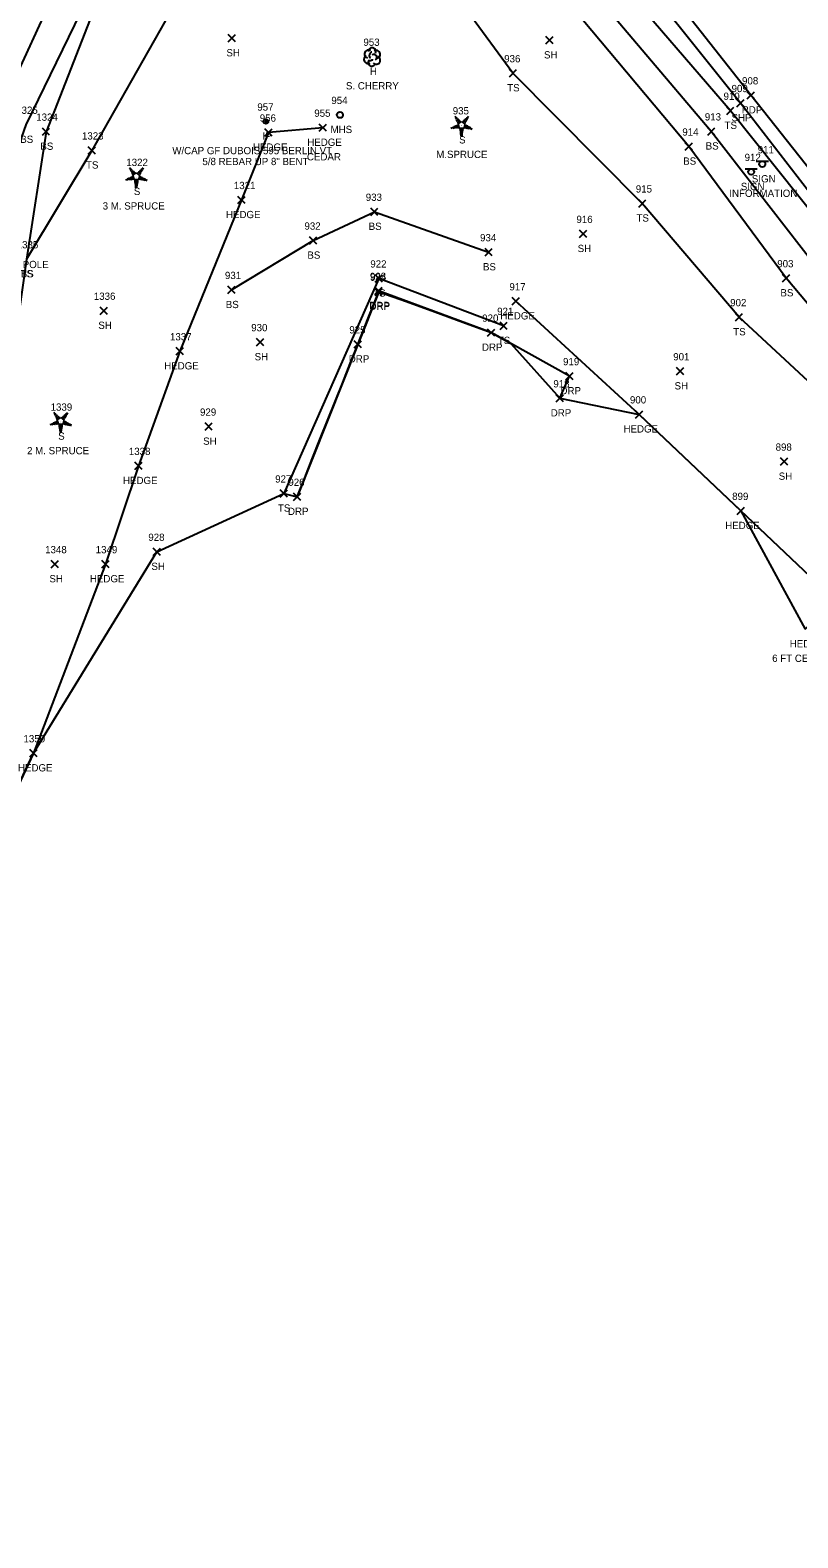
# Model space of a CAD drawing. Extents: x 1623612 to 1625808, y 621345 to 627748.
# Drawn here: x 1624694.8 to 1624906.2, y 625687.8 to 626102.9 of the extents above; entities that cross this region are included whole.
import ezdxf

# ---------------------------------------------------------------- set-up
doc = ezdxf.new("R2010")
doc.units = 0
for name, color, linetype in [('L_A', 7, 'Continuous'), ('L_C', 7, 'Continuous'), ('L_I', 7, 'Continuous'), ('L_TIC', 7, 'Continuous'), ('LAHR', 7, 'Continuous'), ('LELB', 7, 'Continuous'), ('LSOGP', 7, 'Continuous'), ('LTC', 7, 'Continuous'), ('LTD', 7, 'Continuous'), ('M_A', 7, 'Continuous'), ('M_C', 7, 'Continuous'), ('M_I', 7, 'Continuous'), ('MPIR', 7, 'Continuous'), ('P_A', 7, 'Continuous'), ('P_I', 7, 'Continuous'), ('P_TIC', 7, 'Continuous'), ('PET', 7, 'Continuous'), ('PSP', 7, 'Continuous'), ('R_A', 7, 'Continuous'), ('R_I', 7, 'Continuous'), ('R_TIC', 7, 'Continuous'), ('RDP', 7, 'Continuous'), ('S_A', 7, 'Continuous'), ('S_C', 7, 'Continuous'), ('S_I', 7, 'Continuous'), ('SSGN', 7, 'Continuous'), ('U_A', 7, 'Continuous'), ('U_I', 7, 'Continuous'), ('USMH', 7, 'Continuous')]:
    doc.layers.add(name, color=color, linetype=linetype)

msp = doc.modelspace()

# ---------------------------------------------------------------- linework, layer by layer
at = {"layer": 'L_TIC'}
for points in [[(1624749.37, 626099.7), (1624751.37, 626101.7)], [(1624751.37, 626099.7), (1624749.37, 626101.7)], [(1624836.83, 626099.13), (1624838.83, 626101.13)], [(1624838.83, 626099.13), (1624836.83, 626101.13)], [(1624826.77, 626090.06), (1624828.77, 626092.06)], [(1624828.77, 626090.06), (1624826.77, 626092.06)], [(1624886.64, 626079.72), (1624888.64, 626081.72)], [(1624888.64, 626079.72), (1624886.64, 626081.72)], [(1624774.42, 626075.07), (1624776.42, 626077.07)], [(1624776.42, 626075.07), (1624774.42, 626077.07)], [(1624698.16, 626073.97), (1624700.16, 626075.97)], [(1624700.16, 626073.97), (1624698.16, 626075.97)], [(1624759.46, 626073.73), (1624761.46, 626075.73)], [(1624761.46, 626073.73), (1624759.46, 626075.73)], [(1624881.4, 626074.05), (1624883.4, 626076.05)], [(1624883.4, 626074.05), (1624881.4, 626076.05)], [(1624710.77, 626068.81), (1624712.77, 626070.81)], [(1624712.77, 626068.81), (1624710.77, 626070.81)], [(1624875.22, 626069.88), (1624877.22, 626071.88)], [(1624877.22, 626069.88), (1624875.22, 626071.88)], [(1624752.03, 626055.16), (1624754.03, 626057.16)], [(1624754.03, 626055.16), (1624752.03, 626057.16)], [(1624862.39, 626054.21), (1624864.39, 626056.21)], [(1624864.39, 626054.21), (1624862.39, 626056.21)], [(1624788.59, 626051.92), (1624790.59, 626053.92)], [(1624790.59, 626051.92), (1624788.59, 626053.92)], [(1624846.1, 626045.82), (1624848.1, 626047.82)], [(1624848.1, 626045.82), (1624846.1, 626047.82)], [(1624771.71, 626043.99), (1624773.71, 626045.99)], [(1624773.71, 626043.99), (1624771.71, 626045.99)], [(1624820.07, 626040.79), (1624822.07, 626042.79)], [(1624822.07, 626040.79), (1624820.07, 626042.79)], [(1624789.84, 626033.56), (1624791.84, 626035.56)], [(1624791.84, 626033.56), (1624789.84, 626035.56)], [(1624902, 626033.62), (1624904, 626035.62)], [(1624904, 626033.62), (1624902, 626035.62)], [(1624749.23, 626030.39), (1624751.23, 626032.39)], [(1624751.23, 626030.39), (1624749.23, 626032.39)], [(1624827.59, 626027.27), (1624829.59, 626029.27)], [(1624829.59, 626027.27), (1624827.59, 626029.27)], [(1624714.08, 626024.67), (1624716.08, 626026.67)], [(1624716.08, 626024.67), (1624714.08, 626026.67)], [(1624889.03, 626022.9), (1624891.03, 626024.9)], [(1624891.03, 626022.9), (1624889.03, 626024.9)], [(1624824.2, 626020.51), (1624826.2, 626022.51)], [(1624826.2, 626020.51), (1624824.2, 626022.51)], [(1624735.01, 626013.51), (1624737.01, 626015.51)], [(1624737.01, 626013.51), (1624735.01, 626015.51)], [(1624757.13, 626016.02), (1624759.13, 626018.02)], [(1624759.13, 626016.02), (1624757.13, 626018.02)], [(1624872.79, 626008), (1624874.79, 626010)], [(1624874.79, 626008), (1624872.79, 626010)], [(1624861.52, 625996.14), (1624863.52, 625998.14)], [(1624863.52, 625996.14), (1624861.52, 625998.14)], [(1624742.95, 625992.77), (1624744.95, 625994.77)], [(1624744.95, 625992.77), (1624742.95, 625994.77)], [(1624723.67, 625981.95), (1624725.67, 625983.95)], [(1624725.67, 625981.95), (1624723.67, 625983.95)], [(1624901.47, 625983.13), (1624903.47, 625985.13)], [(1624903.47, 625983.13), (1624901.47, 625985.13)], [(1624763.64, 625974.36), (1624765.64, 625976.36)], [(1624765.64, 625974.36), (1624763.64, 625976.36)], [(1624889.51, 625969.57), (1624891.51, 625971.57)], [(1624891.51, 625969.57), (1624889.51, 625971.57)], [(1624700.61, 625954.9), (1624702.61, 625956.9)], [(1624702.61, 625954.9), (1624700.61, 625956.9)], [(1624714.54, 625954.9), (1624716.54, 625956.9)], [(1624716.54, 625954.9), (1624714.54, 625956.9)], [(1624728.7, 625958.31), (1624730.7, 625960.31)], [(1624730.7, 625958.31), (1624728.7, 625960.31)], [(1624694.74, 625902.84), (1624696.74, 625904.84)], [(1624696.74, 625902.84), (1624694.74, 625904.84)]]:
    msp.add_lwpolyline(points, dxfattribs=at)
at = {"layer": 'LAHR'}
for points in [[(1624775.42, 626076.07), (1624760.46, 626074.73), (1624753.03, 626056.16), (1624736.01, 626014.51), (1624724.67, 625982.95), (1624715.54, 625955.9), (1624695.74, 625903.84), (1624670.26, 625849.95), (1624662.52, 625817.48), (1624651.69, 625796.18)], [(1624908.29, 625937.99), (1624916.64, 625945.86), (1624890.51, 625970.57), (1624862.52, 625997.14), (1624828.59, 626028.27)]]:
    msp.add_lwpolyline(points, dxfattribs=at)
at = {"layer": 'LELB'}
for points in [[(1624922.62, 625919.78), (1624947.1, 625948.56), (1624957.29, 625967.96), (1624961.07, 625979.24), (1624958.14, 625988.32), (1624939.98, 626014.97), (1624913.35, 626048.53), (1624887.64, 626080.72), (1624849.69, 626124.89), (1624827.87, 626147.28), (1624809.41, 626168.54), (1624784.36, 626180.38), (1624768.54, 626181.82), (1624752.66, 626178.59), (1624735.62, 626165.38), (1624717.35, 626142.72), (1624703.97, 626118.88), (1624686.38, 626080.62)], [(1624955.96, 625983.78), (1624934.11, 626011.11), (1624911.27, 626037.79), (1624882.4, 626075.05), (1624844.35, 626119.9), (1624824.36, 626144.8), (1624806.17, 626164.83), (1624787.45, 626176.55), (1624783.93, 626178.73), (1624767.98, 626179.73), (1624754.07, 626176), (1624742, 626162.74), (1624739.77, 626159.16), (1624724.1, 626139.19), (1624712.05, 626114.81), (1624693.63, 626076.88), (1624682.43, 626045.31), (1624675.97, 626009.13), (1624661.01, 625972.63), (1624643.83, 625915.97), (1624628.3, 625870.19), (1624627.01, 625849.3)], [(1624955.96, 625983.78), (1624951.7, 625981.09), (1624926.74, 626006.44), (1624903, 626034.62), (1624876.22, 626070.88), (1624844.75, 626108.46), (1624819.16, 626140.11), (1624799.87, 626157.38), (1624783.22, 626162.54), (1624755.55, 626163.6), (1624745.94, 626159.17), (1624742.5, 626157.44), (1624728.24, 626136.03), (1624714.3, 626113.6), (1624699.16, 626074.97), (1624693.78, 626039.85), (1624688.78, 626004.07), (1624672.44, 625966.06), (1624654.5, 625913.12), (1624647.49, 625863.39), (1624632.05, 625839.96), (1624633.8, 625804.37), (1624607.9, 625781.97), (1624576.85, 625750.09)], [(1624950.51, 625967.41), (1624917.97, 625998.05), (1624890.03, 626023.9), (1624863.39, 626055.21), (1624827.77, 626091.06), (1624802.93, 626124.92), (1624791, 626136.13), (1624749.2, 626141.33), (1624736.73, 626113.9), (1624711.77, 626069.81), (1624693.78, 626039.85)], [(1624750.23, 626031.39), (1624772.71, 626044.99), (1624789.59, 626052.92), (1624821.07, 626041.79)], [(1624825.2, 626021.51), (1624790.84, 626034.56), (1624764.64, 625975.36)]]:
    msp.add_lwpolyline(points, dxfattribs=at)
at = {"layer": 'LSOGP'}
msp.add_lwpolyline([(1624670.26, 625849.95), (1624695.74, 625903.84), (1624729.7, 625959.31), (1624764.64, 625975.36), (1624768.33, 625974.45), (1624770.42, 625979.69), (1624772.51, 625984.94), (1624774.6, 625990.19), (1624776.69, 625995.43), (1624778.79, 626000.68), (1624780.88, 626005.93), (1624782.97, 626011.18), (1624785.06, 626016.42), (1624787.93, 626023.66), (1624790.79, 626030.91), (1624798.48, 626028.25), (1624806.24, 626025.38), (1624813.99, 626022.51), (1624821.75, 626019.64), (1624827.15, 626016.64), (1624840.69, 626001.56), (1624862.52, 625997.14), (1624890.51, 625970.57), (1624908.29, 625937.99)], dxfattribs=at)
at = {"layer": 'LTC'}
for p, q in [((1624811.74, 626078.92), (1624812.09, 626079.18)), ((1624811.95, 626078.46), (1624812.48, 626078.84)), ((1624812.14, 626076.85), (1624812.47, 626075.83)), ((1624812.16, 626077.99), (1624812.86, 626078.5)), ((1624812.37, 626077.53), (1624813.25, 626078.17)), ((1624812.59, 626077.07), (1624813.6, 626077.81)), ((1624812.59, 626077.07), (1624812.98, 626075.88)), ((1624813.6, 626077.81), (1624814.6, 626077.08)), ((1624814.02, 626078.12), (1624814.83, 626077.53)), ((1624814.6, 626077.08), (1624814.21, 626075.88)), ((1624814.4, 626078.47), (1624815.08, 626077.97)), ((1624815.04, 626076.81), (1624814.7, 626075.77)), ((1624814.77, 626078.82), (1624815.32, 626078.42)), ((1624815.14, 626079.17), (1624815.56, 626078.86)), ((1624810.77, 626076.2), (1624810.92, 626075.74)), ((1624811.23, 626076.42), (1624811.44, 626075.77)), ((1624811.68, 626076.64), (1624811.95, 626075.8)), ((1624814.21, 626075.88), (1624812.98, 626075.88)), ((1624814.17, 626075.38), (1624813.03, 626075.38)), ((1624814.09, 626074.88), (1624813.1, 626074.88)), ((1624814, 626074.38), (1624813.17, 626074.38)), ((1624813.92, 626073.88), (1624813.25, 626073.88)), ((1624815.48, 626076.56), (1624815.2, 626075.68)), ((1624815.93, 626076.31), (1624815.69, 626075.58)), ((1624816.37, 626076.06), (1624816.19, 626075.49)), ((1624722.16, 626064.74), (1624722.52, 626065)), ((1624722.37, 626064.28), (1624722.9, 626064.66)), ((1624722.58, 626063.81), (1624723.29, 626064.32)), ((1624724.82, 626064.29), (1624725.5, 626063.79)), ((1624725.19, 626064.63), (1624725.74, 626064.23)), ((1624725.56, 626064.98), (1624725.98, 626064.68)), ((1624721.2, 626062.02), (1624721.35, 626061.55)), ((1624721.65, 626062.24), (1624721.86, 626061.59)), ((1624722.11, 626062.45), (1624722.38, 626061.62)), ((1624722.56, 626062.67), (1624722.89, 626061.65)), ((1624722.79, 626063.34), (1624723.67, 626063.98)), ((1624723.02, 626062.89), (1624724.03, 626063.62)), ((1624723.02, 626062.89), (1624723.4, 626061.7)), ((1624724.63, 626061.7), (1624723.4, 626061.7)), ((1624724.6, 626061.2), (1624723.45, 626061.2)), ((1624724.51, 626060.7), (1624723.52, 626060.7)), ((1624724.43, 626060.2), (1624723.6, 626060.2)), ((1624724.03, 626063.62), (1624725.03, 626062.9)), ((1624724.45, 626063.94), (1624725.26, 626063.35)), ((1624725.03, 626062.9), (1624724.63, 626061.7)), ((1624725.46, 626062.63), (1624725.13, 626061.59)), ((1624725.91, 626062.38), (1624725.62, 626061.49)), ((1624726.35, 626062.13), (1624726.12, 626061.4)), ((1624726.8, 626061.88), (1624726.61, 626061.3)), ((1624724.34, 626059.7), (1624723.67, 626059.7)), ((1624700.36, 625994.63), (1624700.52, 625994.16)), ((1624700.82, 625994.85), (1624701.03, 625994.2)), ((1624701.27, 625995.07), (1624701.55, 625994.23)), ((1624701.33, 625997.35), (1624701.69, 625997.61)), ((1624701.54, 625996.89), (1624702.07, 625997.27)), ((1624701.73, 625995.28), (1624702.06, 625994.26)), ((1624701.75, 625996.42), (1624702.45, 625996.93)), ((1624701.96, 625995.96), (1624702.84, 625996.59)), ((1624702.18, 625995.5), (1624703.2, 625996.24)), ((1624702.18, 625995.5), (1624702.57, 625994.31)), ((1624703.8, 625994.31), (1624702.57, 625994.31)), ((1624703.76, 625993.81), (1624702.62, 625993.81)), ((1624703.2, 625996.24), (1624704.19, 625995.51)), ((1624703.62, 625996.55), (1624704.43, 625995.96)), ((1624704.19, 625995.51), (1624703.8, 625994.31)), ((1624703.99, 625996.9), (1624704.67, 625996.4)), ((1624704.63, 625995.24), (1624704.29, 625994.2)), ((1624704.36, 625997.25), (1624704.91, 625996.85)), ((1624704.73, 625997.59), (1624705.15, 625997.29)), ((1624705.07, 625994.99), (1624704.79, 625994.1)), ((1624705.52, 625994.74), (1624705.28, 625994.01)), ((1624705.96, 625994.49), (1624705.78, 625993.91)), ((1624703.68, 625993.31), (1624702.69, 625993.31)), ((1624703.6, 625992.81), (1624702.76, 625992.81)), ((1624703.51, 625992.31), (1624702.84, 625992.31))]:
    msp.add_line(p, q, dxfattribs=at)
at = {"layer": 'LTD'}
msp.add_line((1624788.94, 626095.6), (1624788.94, 626095.6), dxfattribs=at)
msp.add_line((1624788.94, 626095.6), (1624788.94, 626095.6), dxfattribs=at)
msp.add_arc((1624788.99, 626097.04), 1.05, 335.5272, 180.9563, dxfattribs=at)
for centre, major_axis, ratio, start_param, end_param in [((1624788.15, 626096.27), (1.21, -0.51), 0.895232, 1.570796, 4.712389), ((1624789.98, 626096.18), (-1.14, -0.48), 0.949671, 1.570796, 4.712389), ((1624787.86, 626094.89), (0.58, -1.04), 0.959034, 3.141593, 6.283185), ((1624788.94, 626094.1), (0.26, 1.06), 0.942809, 1.570796, 4.712389), ((1624788.48, 626094.85), (-0.625, -0.083), 0.423636, 0, 3.141593), ((1624788.73, 626096.06), (-0.208, -0.792), 0.645439, 3.141593, 6.283185), ((1624789.44, 626095.43), (-0.5, 0.667), 0.989748, 3.141593, 6.283185), ((1624789.94, 626094.77), (-1.09, 0.79), 0.841452, 1.570796, 4.712389)]:
    msp.add_ellipse(centre, major_axis=major_axis, ratio=ratio, start_param=start_param, end_param=end_param, dxfattribs=at)
at = {"layer": 'MPIR'}
for radius in [0.625, 0.0833]:
    msp.add_circle((1624759.73, 626077.76), radius, dxfattribs=at)
at = {"layer": 'P_TIC'}
for points in [[(1624892.3, 626083.98), (1624894.3, 626085.98)], [(1624894.3, 626083.98), (1624892.3, 626085.98)], [(1624889.43, 626081.85), (1624891.43, 626083.85)], [(1624891.43, 626081.85), (1624889.43, 626083.85)]]:
    msp.add_lwpolyline(points, dxfattribs=at)
at = {"layer": 'PET'}
msp.add_lwpolyline([(1625203.84, 625692.06), (1625178.56, 625725.93), (1625159.1, 625752.13), (1625138.75, 625779.51), (1625115.85, 625810.21), (1625086.53, 625849.64), (1625062.28, 625882.29), (1625040.04, 625911.41), (1625011.87, 625940.67), (1624992.38, 625961.15), (1624963.94, 625995.04), (1624945.44, 626018.77), (1624918.36, 626053.4), (1624893.3, 626084.98), (1624858.44, 626129.32)], dxfattribs=at)
at = {"layer": 'PSP'}
msp.add_lwpolyline([(1625197.89, 625687.83), (1625193.57, 625693.81), (1625173.65, 625722.07), (1625153.52, 625749.21), (1625132.81, 625774.23), (1625108.64, 625805.39), (1625079.11, 625843.61), (1625053.93, 625876.29), (1625030.83, 625905.94), (1625006.8, 625934.64), (1624989.43, 625958.35), (1624960.91, 625992.11), (1624942.41, 626016.35), (1624915.38, 626050.56), (1624890.43, 626082.85), (1624855.5, 626126.62)], dxfattribs=at)
at = {"layer": 'R_TIC'}
for points in [[(1624789.73, 626030.13), (1624791.73, 626032.13)], [(1624791.73, 626030.13), (1624789.73, 626032.13)], [(1624789.79, 626029.91), (1624791.79, 626031.91)], [(1624791.79, 626029.91), (1624789.79, 626031.91)], [(1624820.75, 626018.64), (1624822.75, 626020.64)], [(1624822.75, 626018.64), (1624820.75, 626020.64)], [(1624784.06, 626015.42), (1624786.06, 626017.42)], [(1624786.06, 626015.42), (1624784.06, 626017.42)], [(1624842.36, 626006.66), (1624844.36, 626008.66)], [(1624844.36, 626006.66), (1624842.36, 626008.66)], [(1624839.69, 626000.56), (1624841.69, 626002.56)], [(1624841.69, 626000.56), (1624839.69, 626002.56)], [(1624767.33, 625973.45), (1624769.33, 625975.45)], [(1624769.33, 625973.45), (1624767.33, 625975.45)]]:
    msp.add_lwpolyline(points, dxfattribs=at)
at = {"layer": 'RDP'}
msp.add_lwpolyline([(1624840.69, 626001.56), (1624843.36, 626007.66), (1624821.75, 626019.64), (1624790.73, 626031.13), (1624790.79, 626030.91), (1624785.06, 626016.42), (1624768.33, 625974.45)], dxfattribs=at)
at = {"layer": 'SSGN'}
for p, q in [((1624891.74, 626064.74), (1624895.07, 626064.74)), ((1624894.78, 626066.86), (1624898.11, 626066.86)), ((1624896.42, 626066.03), (1624896.42, 626066.03)), ((1624893.38, 626063.91), (1624893.38, 626063.91))]:
    msp.add_line(p, q, dxfattribs=at)
for centre in [(1624893.38, 626063.91), (1624896.42, 626066.03)]:
    msp.add_circle(centre, 0.833, dxfattribs=at)
at = {"layer": 'USMH'}
for p, q in [((1624780.12, 626079.58), (1624780.12, 626079.58)), ((1624780.95, 626079.58), (1624780.95, 626079.58))]:
    msp.add_line(p, q, dxfattribs=at)
msp.add_circle((1624780.12, 626079.58), 0.833, dxfattribs=at)

# ---------------------------------------------------------------- texts
at = {"layer": 'L_A'}
for s, p in [('SH', (1624748.85, 626095.7)), ('SH', (1624836.32, 626095.13)), ('H', (1624788.37, 626090.6)), ('TS', (1624826.18, 626086.06)), ('TS', (1624886.05, 626075.72)), ('BS', (1624692.07, 626071.88)), ('HEDGE', (1624771.12, 626071.07)), ('S', (1624812.93, 626071.72)), ('BS', (1624697.6, 626069.97)), ('HEDGE', (1624756.16, 626069.73)), ('BS', (1624880.85, 626070.05)), ('TS', (1624710.18, 626064.81)), ('BS', (1624874.66, 626065.88)), ('S', (1624723.35, 626057.53)), ('HEDGE', (1624748.73, 626051.16)), ('TS', (1624861.8, 626050.21)), ('BS', (1624788.03, 626047.92)), ('SH', (1624845.59, 626041.82)), ('BS', (1624771.15, 626039.99)), ('TS', (1624692.19, 626034.85)), ('BS', (1624692.22, 626034.85)), ('BS', (1624819.51, 626036.79)), ('TS', (1624789.25, 626029.56)), ('BS', (1624901.44, 626029.62)), ('BS', (1624748.67, 626026.39)), ('HEDGE', (1624824.29, 626023.27)), ('SH', (1624713.57, 626020.67)), ('TS', (1624888.44, 626018.9)), ('TS', (1624823.61, 626016.51)), ('HEDGE', (1624731.71, 626009.51)), ('SH', (1624756.62, 626012.02)), ('SH', (1624872.28, 626004)), ('HEDGE', (1624858.22, 625992.14)), ('S', (1624702.52, 625990.15)), ('SH', (1624742.44, 625988.77)), ('HEDGE', (1624720.37, 625977.95)), ('SH', (1624900.96, 625979.13)), ('TS', (1624763.05, 625970.36)), ('HEDGE', (1624886.22, 625965.57)), ('SH', (1624728.19, 625954.31)), ('SH', (1624700.1, 625950.9)), ('HEDGE', (1624711.24, 625950.9)), ('HEDGE', (1624903.99, 625932.99)), ('HEDGE', (1624691.44, 625898.84))]:
    msp.add_text(s, height=2, dxfattribs=at).set_placement(p)
at = {"layer": 'L_C'}
for s, p in [('S. CHERRY', (1624781.76, 626086.6)), ('CEDAR', (1624771.03, 626067.07)), ('M.SPRUCE', (1624806.63, 626067.72)), ('3 M. SPRUCE', (1624714.77, 626053.53)), ('2 M. SPRUCE', (1624693.94, 625986.15)), ('6 FT CEDAR', (1624899.16, 625928.99))]:
    msp.add_text(s, height=2, dxfattribs=at).set_placement(p)
at = {"layer": 'L_I'}
for s, p in [('953', (1624786.58, 626098.6)), ('936', (1624825.35, 626094.06)), ('910', (1624885.76, 626083.72)), ('1325', (1624690.94, 626079.88)), ('955', (1624773.05, 626079.07)), ('935', (1624811.18, 626079.72)), ('1324', (1624696.47, 626077.97)), ('956', (1624758.04, 626077.73)), ('913', (1624880.61, 626078.05)), ('1323', (1624709.07, 626072.81)), ('914', (1624874.42, 626073.88)), ('1322', (1624721.28, 626065.53)), ('1321', (1624750.9, 626059.16)), ('915', (1624861.6, 626058.21)), ('933', (1624787.23, 626055.92)), ('916', (1624845.25, 626049.82)), ('932', (1624770.34, 626047.99)), ('1335', (1624691.09, 626042.85)), ('1335', (1624691.09, 626042.85)), ('934', (1624818.71, 626044.79)), ('922', (1624788.48, 626037.56)), ('903', (1624900.56, 626037.62)), ('931', (1624748.44, 626034.39)), ('917', (1624826.79, 626031.27)), ('1336', (1624712.33, 626028.67)), ('902', (1624887.59, 626026.9)), ('921', (1624823.41, 626024.51)), ('1337', (1624733.31, 626017.51)), ('930', (1624755.68, 626020.02)), ('901', (1624871.91, 626012)), ('900', (1624859.99, 626000.14)), ('1339', (1624700.43, 625998.15)), ('929', (1624741.58, 625996.77)), ('1338', (1624721.98, 625985.95)), ('898', (1624900.11, 625987.13)), ('927', (1624762.28, 625978.36)), ('899', (1624888.14, 625973.57)), ('1348', (1624698.92, 625958.9)), ('1349', (1624712.84, 625958.9)), ('928', (1624727.34, 625962.31)), ('1350', (1624692.96, 625906.84))]:
    msp.add_text(s, height=2, dxfattribs=at).set_placement(p)
at = {"layer": 'LTC'}
for p in [(1624813.49, 626076.82), (1624723.91, 626062.64), (1624703.08, 625995.25)]:
    msp.add_text('.', height=1.04, rotation=270, dxfattribs=at).set_placement(p)
at = {"layer": 'M_A'}
msp.add_text('IP', height=2, dxfattribs=at).set_placement((1624758.77, 626072.76))
at = {"layer": 'M_C'}
for s, p in [('W/CAP GF DUBOIS 595 BERLIN VT', (1624733.95, 626068.76)), ('5/8 REBAR UP 8" BENT', (1624742.24, 626065.76))]:
    msp.add_text(s, height=2, dxfattribs=at).set_placement(p)
at = {"layer": 'M_I'}
msp.add_text('957', height=2, dxfattribs=at).set_placement((1624757.36, 626080.76))
at = {"layer": 'P_A'}
for s, p in [('RDP', (1624890.79, 626079.98)), ('SHP', (1624887.97, 626077.85))]:
    msp.add_text(s, height=2, dxfattribs=at).set_placement(p)
at = {"layer": 'P_I'}
for s, p in [('908', (1624890.86, 626087.98)), ('909', (1624887.98, 626085.85))]:
    msp.add_text(s, height=2, dxfattribs=at).set_placement(p)
at = {"layer": 'R_A'}
for p in [(1624788.22, 626026.13), (1624788.28, 626025.91), (1624819.23, 626014.64), (1624782.55, 626011.42), (1624840.85, 626002.66), (1624838.18, 625996.56), (1624765.81, 625969.45)]:
    msp.add_text('DRP', height=2, dxfattribs=at).set_placement(p)
at = {"layer": 'R_I'}
for s, p in [('923', (1624788.37, 626034.13)), ('924', (1624788.43, 626033.91)), ('920', (1624819.3, 626022.64)), ('925', (1624782.7, 626019.42)), ('919', (1624841.56, 626010.66)), ('918', (1624838.89, 626004.56)), ('926', (1624765.91, 625977.45))]:
    msp.add_text(s, height=2, dxfattribs=at).set_placement(p)
at = {"layer": 'S_A'}
for p in [(1624890.52, 626058.89), (1624893.56, 626061.01)]:
    msp.add_text('SIGN', height=2, dxfattribs=at).set_placement(p)
at = {"layer": 'S_C'}
for s, p in [('INFORMATION', (1624887.36, 626057.01)), ('OVERHEAD SIGN SUPPORT POLE', (1624656.04, 626037.41))]:
    msp.add_text(s, height=2, dxfattribs=at).set_placement(p)
at = {"layer": 'S_I'}
for s, p in [('912', (1624891.57, 626066.89)), ('911', (1624895.17, 626069.01))]:
    msp.add_text(s, height=2, dxfattribs=at).set_placement(p)
at = {"layer": 'U_A'}
msp.add_text('MHS', height=2, dxfattribs=at).set_placement((1624777.53, 626074.58))
at = {"layer": 'U_I'}
msp.add_text('954', height=2, dxfattribs=at).set_placement((1624777.75, 626082.58))

doc.saveas('drawing.dxf')
